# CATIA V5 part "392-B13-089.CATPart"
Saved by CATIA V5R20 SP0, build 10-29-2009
Part number: 392-B13-089
Definition: NONE
Nomenclature: 392-B13-089
Source: Unknown
Description: 392-B13-089
Bounding box of the stored display mesh (mm): x 0 to 89, y -6.145 to 6.145, z -6.1 to 5.947
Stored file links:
  C:\Users\Utente\Desktop\IO LAVORO\3D X SITO CF\X SITO\3D files 392B\392-B13-089.CATPart
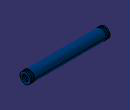
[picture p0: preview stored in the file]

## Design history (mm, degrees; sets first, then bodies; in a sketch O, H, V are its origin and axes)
Body1 "392-B13-089" (main body)
  Solid1: solid without history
